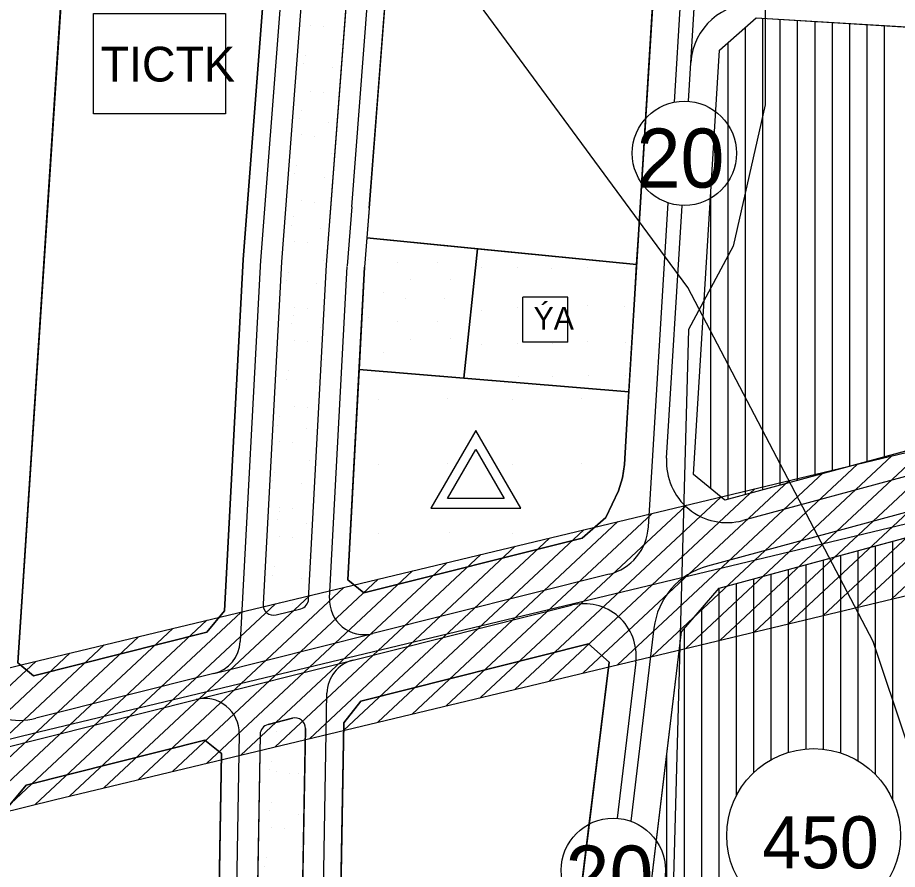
# Model space of a CAD drawing. Extents: x 419109 to 421295, y 4452223 to 4457798.
# Drawn here: x 420098 to 420351.1, y 4452707.6 to 4452952.7 of the extents above; entities that cross this region are included whole.
import ezdxf

# ---------------------------------------------------------------- set-up
doc = ezdxf.new("R2010")
doc.units = 0
for name, color, linetype in [('ADA', 7, 'Continuous'), ('ADAKENARI', 7, 'Continuous'), ('Default', 7, 'Continuous'), ('KALDIRIM', 7, 'Continuous'), ('KD_DAIRE', 7, 'Continuous'), ('KD_YGEN', 7, 'Continuous'), ('LJ_SEMBOL', 7, 'Continuous'), ('PL_AYA_PARK_DINLENME', 7, 'Continuous'), ('PL_EĞİTİM', 7, 'Continuous'), ('PL_KON_MEV_450', 7, 'Continuous'), ('PL_SAY_DINI_TESIS', 7, 'Continuous'), ('PL_TİCK', 7, 'Continuous'), ('PL_TURZM', 7, 'Continuous'), ('SM_DAIRE', 7, 'Continuous'), ('SM_SEMBOL', 7, 'Continuous'), ('SM_TAKS', 7, 'Continuous'), ('SN_3_DERECE_KAYNAK_KORUMA', 7, 'Continuous'), ('SN_KENTSEL_DONUSUM', 7, 'Continuous'), ('TA_ENH_154', 7, 'Continuous'), ('TA_ENH_KORUMA', 7, 'Continuous'), ('TA_ENH_TARAMA', 7, 'Continuous'), ('TR_DINITESIS', 7, 'Continuous'), ('TR_EĞİTİM', 7, 'Continuous'), ('TR_PARKALANI', 7, 'Continuous'), ('TR_TİC_TURIZM_K', 7, 'Continuous'), ('TR_TİCK', 7, 'Continuous'), ('TR_YUKSEKYOGUNKONUT', 7, 'Continuous')]:
    doc.layers.add(name, color=color, linetype=linetype)

# ---------------------------------------------------------------- blocks, each defined once
blk = doc.blocks.new('POINT_DISPLAY')
at = {"layer": 'Default'}
blk.add_line((0, 0), (0, 0), dxfattribs=at)

msp = doc.modelspace()

# ---------------------------------------------------------------- linework, layer by layer
at = {"layer": 'ADA'}
for p, q in [((420276.06, 4452881.68), (420198.46, 4452889.32)), ((420226.35, 4452848.98), (420230.3, 4452886.18)), ((420196.24, 4452851.48), (420273.81, 4452845.03))]:
    msp.add_line(p, q, dxfattribs=at)
at = {"layer": 'ADAKENARI'}
for p, q in [((420186.83, 4452881.59), (420205.2, 4453121.18)), ((420199.11, 4452897.8), (420215.59, 4453112.73)), ((420098.01, 4452767.09), (420110.56, 4452958.8)), ((420280.84, 4452959.33), (420276.59, 4452890.16)), ((420168.41, 4452955.24), (420162.88, 4452883.12)), ((420179.38, 4452954.4), (420173.86, 4452882.42)), ((420299.89, 4452943.25), (420310.49, 4452952.62)), ((420310.49, 4452952.62), (420548.29, 4452938.03)), ((420292.38, 4452821.22), (420299.89, 4452943.25)), ((420199.11, 4452897.8), (420197.81, 4452880.85)), ((420276.59, 4452890.16), (420275.54, 4452873.19)), ((420162.88, 4452883.12), (420157.49, 4452782.05)), ((420173.86, 4452882.39), (420168.6, 4452783.92)), ((420181.7, 4452785.39), (420186.83, 4452881.58)), ((420193.01, 4452790.98), (420197.81, 4452880.85)), ((420536.54, 4452877.47), (420301.42, 4452813.85)), ((420275.54, 4452873.19), (420273.34, 4452837.5)), ((420273.34, 4452837.5), (420272.52, 4452824.14)), ((420299.79, 4452788.55), (420467.87, 4452834.02)), ((420272.52, 4452824.14), (420271.98, 4452820.26)), ((420271.98, 4452820.26), (420270.86, 4452816.52)), ((420301.42, 4452813.85), (420292.38, 4452821.22)), ((420270.86, 4452816.52), (420267.24, 4452808.87)), ((420267.24, 4452808.87), (420260.35, 4452802.96)), ((420260.35, 4452802.96), (420197.6, 4452787.2)), ((420197.6, 4452787.2), (420193.01, 4452790.98)), ((420288.95, 4452776.01), (420299.79, 4452788.55)), ((420172.33, 4452780.85), (420179.44, 4452782.64)), ((420157.49, 4452782.05), (420152.37, 4452775.84)), ((420152.37, 4452775.84), (420102.54, 4452763.32)), ((420274.78, 4452657.74), (420288.95, 4452776.01)), ((420196.74, 4452756.05), (420262.23, 4452772.51)), ((420262.23, 4452772.51), (420268.17, 4452767.26)), ((420268.17, 4452767.26), (420253.7, 4452650.28)), ((420102.54, 4452763.32), (420098.01, 4452767.09)), ((420191.81, 4452749.84), (420196.74, 4452756.05)), ((420170.01, 4452749.34), (420177.05, 4452751.11)), ((420189.7, 4452630.41), (420191.81, 4452749.84)), ((420180.78, 4452748.14), (420178.58, 4452623.54)), ((420100.48, 4452731.87), (420151.88, 4452744.79)), ((420151.88, 4452744.79), (420156.65, 4452741.01)), ((420167.74, 4452746.48), (420165.55, 4452622.42)), ((420156.65, 4452741.01), (420154.5, 4452619.21)), ((420095.3, 4452725.67), (420100.48, 4452731.87))]:
    msp.add_line(p, q, dxfattribs=at)
for centre, start, end in [((420178.7, 4452785.55), 284.1002, 356.9459), ((420171.6, 4452783.76), 176.9459, 284.1002), ((420177.78, 4452748.2), 358.9885, 104.1002), ((420170.74, 4452746.43), 104.1002, 178.9885)]:
    msp.add_arc(centre, 3, start, end, dxfattribs=at)
at = {"layer": 'KALDIRIM'}
for p, q in [((420194.12, 4452898.18), (420210.76, 4453115.13)), ((420286.95, 4452928.36), (420293.22, 4453030.14)), ((420290.97, 4452928.59), (420294.36, 4452983.67)), ((420173.39, 4452954.86), (420167.87, 4452882.74)), ((420279.43, 4452806.17), (420285.17, 4452899.37)), ((420194.12, 4452898.18), (420192.82, 4452881.23)), ((420284.65, 4452825.91), (420289.13, 4452898.65)), ((420167.87, 4452882.85), (420162.02, 4452773.16)), ((420187.73, 4452785.7), (420192.82, 4452881.11)), ((420386.64, 4452829.66), (420306.61, 4452808.01)), ((420389.04, 4452819.95), (420296.48, 4452794.91)), ((420268.11, 4452792.54), (420200.15, 4452775.47)), ((420194.52, 4452767.87), (420257.27, 4452783.63)), ((420154.47, 4452764), (420200.15, 4452775.47)), ((420281.01, 4452777.01), (420274.36, 4452721.52)), ((420149.31, 4452756.51), (420194.52, 4452767.87)), ((420275.82, 4452767.3), (420270.43, 4452722.35)), ((420154.47, 4452764), (420103.22, 4452751.12)), ((420184.7, 4452630.5), (420186.96, 4452758.35)), ((420090.4, 4452741.72), (420149.31, 4452756.51)), ((420161.75, 4452746.64), (420159.49, 4452619.12))]:
    msp.add_line(p, q, dxfattribs=at)
for centre, radius, start, end in [((420309.63, 4452938.65), 18, 86.4895, 176.4779), ((420302.06, 4452824.84), 17.44, 176.4779, 285.1389), ((420264.46, 4452807.09), 15, 284.1002, 356.4779), ((420302.01, 4452774.49), 21.15, 105.1389, 173.1692), ((420197.71, 4452785.17), 10, 176.9459, 284.1002), ((420260.92, 4452769.08), 15, 353.1692, 104.1002), ((420152.03, 4452773.69), 10, 284.1002, 356.9459), ((420098.35, 4452770.52), 20, 176.3547, 284.1002), ((420196.96, 4452758.17), 10, 104.1002, 178.9885), ((420151.75, 4452746.81), 10, 358.9885, 104.1002)]:
    msp.add_arc(centre, radius, start, end, dxfattribs=at)
at = {"layer": 'KD_DAIRE'}
for centre in [(420289.8, 4452913.63), (420269.34, 4452707.39)]:
    msp.add_circle(centre, 15, dxfattribs=at)
at = {"layer": 'LJ_SEMBOL'}
msp.add_lwpolyline([(420119.83, 4452953.88), (420157.76, 4452953.88), (420157.76, 4452924.95), (420119.83, 4452924.95)], close=True, dxfattribs=at)
for points in [[(420242.72, 4452811.58), (420229.77, 4452833.9), (420216.83, 4452811.58), (420242.72, 4452811.58)], [(420229.77, 4452828.42), (420237.94, 4452814.33), (420221.6, 4452814.33), (420229.77, 4452828.42)]]:
    msp.add_lwpolyline(points, dxfattribs=at)
at = {"layer": 'PL_AYA_PARK_DINLENME'}
for p, q in [((420173.86, 4452882.39), (420173.86, 4452882.42)), ((420186.83, 4452881.58), (420186.83, 4452881.59)), ((420177.05, 4452751.11), (420170.01, 4452749.34))]:
    msp.add_line(p, q, dxfattribs=at)
for points in [[(420192.37, 4453123.86), (420181.82, 4452986.31), (420179.38, 4452954.4), (420173.86, 4452882.42)], [(420181.7, 4452785.39), (420186.83, 4452881.58), (420205.2, 4453121.18)], [(420198.46, 4452889.32), (420197.81, 4452880.85), (420196.24, 4452851.48), (420226.35, 4452848.98), (420230.3, 4452886.18), (420198.46, 4452889.32)], [(420173.86, 4452882.42), (420173.86, 4452882.39), (420168.6, 4452783.92)], [(420172.33, 4452780.85), (420179.44, 4452782.64)], [(420221.98, 4452467.28), (420213.84, 4452479.19), (420203.09, 4452493.61), (420194.84, 4452512.71), (420190.3, 4452526.4), (420187.84, 4452538.01), (420184.31, 4452554.71), (420180.74, 4452571.59), (420178.77, 4452588.31), (420178.65, 4452601.88), (420178.58, 4452623.54), (420180.78, 4452748.14)], [(420167.74, 4452746.48), (420165.55, 4452622.42), (420165.66, 4452600.54), (420165.78, 4452587.49), (420167.9, 4452569.48), (420177.73, 4452523), (420182.68, 4452508.07), (420190.47, 4452490.05), (420208.04, 4452455.12), (420231.59, 4452419.21), (420246, 4452397.23), (420275.85, 4452353.52), (420315.27, 4452293.39)]]:
    msp.add_lwpolyline(points, dxfattribs=at)
for centre, start, end in [((420178.7, 4452785.55), 284.1002, 356.9459), ((420171.6, 4452783.76), 176.9459, 284.1002), ((420177.78, 4452748.2), 358.9885, 104.1002), ((420170.74, 4452746.43), 104.1002, 178.9885)]:
    msp.add_arc(centre, 3, start, end, dxfattribs=at)
at = {"layer": 'PL_EĞİTİM'}
msp.add_lwpolyline([(420196.24, 4452851.48), (420193.01, 4452790.98), (420197.6, 4452787.2), (420260.35, 4452802.96), (420267.24, 4452808.87), (420270.86, 4452816.52), (420271.98, 4452820.26), (420272.52, 4452824.14), (420273.34, 4452837.5), (420273.81, 4452845.03), (420226.35, 4452848.98), (420196.24, 4452851.48)], dxfattribs=at)
at = {"layer": 'PL_KON_MEV_450'}
for points in [[(420310.49, 4452952.62), (420548.29, 4452938.03), (420556.21, 4452927.64), (420548.25, 4452889.86), (420536.54, 4452877.47), (420301.42, 4452813.85), (420292.38, 4452821.22), (420299.89, 4452943.25)], [(420299.79, 4452788.55), (420467.87, 4452834.02), (420464.63, 4452792.44), (420385.14, 4452799.11), (420376.66, 4452726.13), (420364.66, 4452632.46), (420451.75, 4452625.1), (420449.42, 4452575.56), (420449.42, 4452560.62), (420361.09, 4452604.42), (420282.55, 4452643.37), (420274.78, 4452657.74), (420288.95, 4452776.01)]]:
    msp.add_lwpolyline(points, close=True, dxfattribs=at)
at = {"layer": 'PL_SAY_DINI_TESIS'}
msp.add_lwpolyline([(420273.81, 4452845.03), (420275.54, 4452873.19), (420276.06, 4452881.68), (420230.3, 4452886.18), (420226.35, 4452848.98), (420273.81, 4452845.03)], dxfattribs=at)
at = {"layer": 'PL_TİCK'}
for points in [[(420276.06, 4452881.68), (420276.59, 4452890.16), (420280.84, 4452959.33), (420282.07, 4452979.3), (420284.65, 4453021.25), (420285.88, 4453041.22), (420287.88, 4453073.74), (420279.7, 4453088.47), (420225.15, 4453117.94), (420215.59, 4453112.73), (420199.11, 4452897.8), (420198.46, 4452889.32), (420230.3, 4452886.18), (420276.06, 4452881.68)], [(420253.7, 4452650.28), (420268.17, 4452767.26), (420262.23, 4452772.51), (420196.74, 4452756.05), (420191.81, 4452749.84), (420189.7, 4452630.41), (420189.6, 4452607.8), (420189.77, 4452589), (420190.03, 4452586.79), (420276.74, 4452528.45)]]:
    msp.add_lwpolyline(points, dxfattribs=at)
at = {"layer": 'PL_TURZM'}
for points in [[(420122.39, 4453139.62), (420122.16, 4453136.1), (420112.64, 4452990.73), (420110.56, 4452958.8), (420098.01, 4452767.09), (420102.54, 4452763.32), (420152.37, 4452775.84), (420157.49, 4452782.05), (420162.88, 4452883.12), (420168.41, 4452955.24), (420170.86, 4452987.15), (420181.47, 4453125.59), (420181.74, 4453129.1), (420177.2, 4453134.96), (420127.64, 4453143.73), (420122.39, 4453139.62)], [(420225.97, 4452407.72), (420222.39, 4452413.18), (420198.5, 4452449.62), (420180.5, 4452485.39), (420172.39, 4452504.15), (420167.1, 4452520.12), (420157.04, 4452567.7), (420154.79, 4452586.79), (420154.7, 4452596.71), (420154.5, 4452619.21), (420156.65, 4452741.01), (420151.88, 4452744.79), (420100.48, 4452731.87), (420095.3, 4452725.67)]]:
    msp.add_lwpolyline(points, dxfattribs=at)
at = {"layer": 'SM_DAIRE'}
msp.add_circle((420326.96, 4452717.38), 25, dxfattribs=at)
at = {"layer": 'SM_SEMBOL'}
for points in [[(420256.29, 4452872.28), (420243.29, 4452872.28)], [(420243.29, 4452859.28), (420243.29, 4452872.28)], [(420256.29, 4452859.28), (420256.29, 4452872.28)], [(420256.29, 4452859.28), (420243.29, 4452859.28)]]:
    msp.add_lwpolyline(points, dxfattribs=at)
at = {"layer": 'SN_3_DERECE_KAYNAK_KORUMA'}
msp.add_lwpolyline([(420357.81, 4452232.59), (420364.57, 4452258.77), (420388.14, 4452395.87), (420395.04, 4452520.02), (420383.4, 4452655.62), (420344.11, 4452773.22), (420290.77, 4452875.07), (420213.22, 4452980.45), (420010.57, 4453225.26), (419772.92, 4453473.96), (419554.68, 4453657.1), (419332.55, 4453805.23), (419159.82, 4453894.89), (419126.5, 4453906.07)], dxfattribs=at)
at = {"layer": 'SN_KENTSEL_DONUSUM'}
for p, q in [((420313.06, 4453004.98), (420313.06, 4452927.53)), ((420313.06, 4452927.53), (420303.84, 4452886.96)), ((420303.84, 4452886.96), (420290.93, 4452862.98)), ((420290.93, 4452862.98), (420285.4, 4452658.29))]:
    msp.add_line(p, q, dxfattribs=at)
at = {"layer": 'TA_ENH_154'}
msp.add_lwpolyline([(421244.23, 4452871.73), (420603.45, 4452866.93), (420104.11, 4452747.15), (419709.07, 4452649.72), (419353.3, 4452559.56), (419284.53, 4452601.29), (419287.68, 4452599.87), (419484.08, 4452691.72), (419833.95, 4454863.94), (419862.83, 4455014.24)], dxfattribs=at)
at = {"layer": 'TA_ENH_KORUMA'}
msp.add_lwpolyline([(419883.15, 4455014.02), (419853.65, 4454860.46), (419502.14, 4452678.09), (419329.55, 4452597.37), (419356.51, 4452581.01), (419704.22, 4452669.12), (420099.38, 4452766.58), (420601.01, 4452886.92), (421244.44, 4452891.74)], dxfattribs=at)
at = {"layer": 'TA_ENH_TARAMA'}
for p, q in [((420108.84, 4452727.71), (420605.89, 4452846.95)), ((420349.39, 4452785.42), (420408.61, 4452840.76)), ((420339.54, 4452783.05), (420398.76, 4452838.4)), ((420329.69, 4452780.69), (420388.91, 4452836.03)), ((420319.83, 4452778.33), (420379.05, 4452833.67)), ((420309.98, 4452775.96), (420369.2, 4452831.31)), ((420300.13, 4452773.6), (420359.35, 4452828.94)), ((420290.28, 4452771.24), (420349.5, 4452826.58)), ((420280.42, 4452768.87), (420339.64, 4452824.22)), ((420270.57, 4452766.51), (420329.79, 4452821.85)), ((420260.72, 4452764.15), (420319.94, 4452819.49)), ((420250.87, 4452761.78), (420310.09, 4452817.13)), ((420241.02, 4452759.42), (420300.23, 4452814.76)), ((420231.16, 4452757.06), (420290.38, 4452812.4)), ((420211.46, 4452752.33), (420270.68, 4452807.67)), ((420221.31, 4452754.69), (420280.53, 4452810.04)), ((420201.61, 4452749.96), (420260.82, 4452805.31)), ((420191.75, 4452747.6), (420250.97, 4452802.95)), ((420181.9, 4452745.24), (420241.12, 4452800.58)), ((420172.05, 4452742.87), (420231.27, 4452798.22)), ((420162.2, 4452740.51), (420221.42, 4452795.86)), ((420152.34, 4452738.15), (420211.56, 4452793.49)), ((420142.49, 4452735.78), (420201.71, 4452791.13)), ((420132.64, 4452733.42), (420191.86, 4452788.77)), ((420122.79, 4452731.06), (420182.01, 4452786.4)), ((420112.93, 4452728.69), (420172.15, 4452784.04)), ((420103.03, 4452726.28), (420162.3, 4452781.68)), ((420093.08, 4452723.82), (420152.45, 4452779.31)), ((420083.13, 4452721.37), (420142.6, 4452776.95)), ((420063.23, 4452716.46), (420122.89, 4452772.22)), ((420073.18, 4452718.92), (420132.74, 4452774.58)), ((420053.28, 4452714.01), (420113.04, 4452769.86)), ((420043.33, 4452711.56), (420103.19, 4452767.49)), ((419713.92, 4452630.31), (420108.84, 4452727.71))]:
    msp.add_line(p, q, dxfattribs=at)
at = {"layer": 'TR_TİC_TURIZM_K'}
for points in [[(420127.64, 4453143.73), (420122.39, 4453139.62), (420122.16, 4453136.1), (420112.64, 4452990.73), (420110.56, 4452958.8), (420098.01, 4452767.09), (420102.54, 4452763.32), (420152.37, 4452775.84), (420157.49, 4452782.05), (420162.88, 4452883.12), (420168.41, 4452955.24), (420170.86, 4452987.15), (420181.47, 4453125.59), (420181.74, 4453129.1), (420177.2, 4453134.96), (420127.64, 4453143.73)], [(420119.83, 4452924.95), (420119.83, 4452953.88), (420157.76, 4452953.88), (420157.76, 4452924.95), (420119.83, 4452924.95)], [(420093.03, 4452576.93), (420100.03, 4452536.75), (420107.76, 4452506.59), (420114.48, 4452486.76), (420120.64, 4452471), (420129.77, 4452449.56), (420138.18, 4452433.13), (420173.92, 4452366.16), (420177.01, 4452360.38), (420225.97, 4452407.72), (420222.39, 4452413.18), (420198.5, 4452449.62), (420180.5, 4452485.39), (420172.39, 4452504.15), (420167.1, 4452520.12), (420157.04, 4452567.7), (420154.79, 4452586.79), (420154.7, 4452596.71), (420154.5, 4452619.21), (420156.65, 4452741.01), (420151.88, 4452744.79), (420100.48, 4452731.87), (420095.3, 4452725.67)]]:
    msp.add_lwpolyline(points, dxfattribs=at)
at = {"layer": 'TR_TİCK'}
for points in [[(420276.06, 4452881.68), (420276.59, 4452890.16), (420280.84, 4452959.33), (420282.07, 4452979.3), (420284.65, 4453021.25), (420285.88, 4453041.22), (420287.88, 4453073.74), (420279.7, 4453088.47), (420225.15, 4453117.94), (420215.59, 4453112.73), (420199.11, 4452897.8), (420198.46, 4452889.32), (420230.3, 4452886.18), (420276.06, 4452881.68)], [(420253.7, 4452650.28), (420268.17, 4452767.26), (420262.23, 4452772.51), (420196.74, 4452756.05), (420191.81, 4452749.84), (420189.7, 4452630.41), (420189.6, 4452607.8), (420189.77, 4452589), (420190.03, 4452586.79), (420276.74, 4452528.45)]]:
    msp.add_lwpolyline(points, dxfattribs=at)
at = {"layer": 'TR_YUKSEKYOGUNKONUT'}
for p, q in [((420312.38, 4452816.82), (420312.38, 4452952.51)), ((420317.38, 4452818.17), (420317.38, 4452952.2)), ((420322.38, 4452819.53), (420322.38, 4452951.89)), ((420307.38, 4452815.47), (420307.38, 4452949.88)), ((420327.38, 4452820.88), (420327.38, 4452951.59)), ((420332.38, 4452822.23), (420332.38, 4452951.28)), ((420337.38, 4452823.58), (420337.38, 4452950.97)), ((420342.38, 4452824.94), (420342.38, 4452950.67)), ((420347.38, 4452826.29), (420347.38, 4452950.36)), ((420302.38, 4452814.11), (420302.38, 4452945.45)), ((420297.38, 4452817.15), (420297.38, 4452902.46)), ((420344.78, 4452734.92), (420344.78, 4452800.72)), ((420349.78, 4452727.59), (420349.78, 4452802.08)), ((420334.78, 4452741.13), (420334.78, 4452798.02)), ((420339.78, 4452738.84), (420339.78, 4452799.37)), ((420324.78, 4452742.29), (420324.78, 4452795.31)), ((420329.78, 4452742.22), (420329.78, 4452796.66)), ((420314.78, 4452739.21), (420314.78, 4452792.61)), ((420319.78, 4452741.33), (420319.78, 4452793.96)), ((420304.78, 4452728.91), (420304.78, 4452789.9)), ((420309.78, 4452735.54), (420309.78, 4452791.25)), ((420299.78, 4452634.82), (420299.78, 4452788.54)), ((420294.78, 4452637.3), (420294.78, 4452782.76)), ((420289.78, 4452639.78), (420289.78, 4452776.97)), ((420284.78, 4452642.26), (420284.78, 4452741.22))]:
    msp.add_line(p, q, dxfattribs=at)

# ---------------------------------------------------------------- block references
at = {"layer": 'TR_DINITESIS', "xscale": 0.1, "yscale": 0.10000000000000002}
for p in [(420231.5, 4452880.81), (420241.75, 4452880.81), (420251.51, 4452880.62), (420261.85, 4452880.81), (420272.49, 4452880.78), (420231.5, 4452868.52), (420241.75, 4452869.34), (420251.51, 4452869.43), (420261.85, 4452869.72), (420272.49, 4452869.59), (420231.5, 4452858.52), (420241.75, 4452859.01), (420251.89, 4452859.01), (420261.85, 4452859.48), (420272.87, 4452859.17), (420231.82, 4452848.51), (420242.07, 4452849.33), (420251.84, 4452849.43), (420262.17, 4452849.71), (420272.81, 4452849.59)]:
    msp.add_blockref('POINT_DISPLAY', p, dxfattribs=at)
at = {"layer": 'TR_EĞİTİM', "xscale": 0.1, "yscale": 0.10000000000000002}
for p in [(420201.92, 4452842.77), (420221.67, 4452843), (420240.48, 4452842.77), (420260.23, 4452843), (420201.92, 4452824.19), (420221.67, 4452824.41), (420240.48, 4452824.19), (420260.23, 4452824.41), (420201.92, 4452804.19), (420222.12, 4452804.5), (420240.48, 4452804.19), (420260.68, 4452804.5)]:
    msp.add_blockref('POINT_DISPLAY', p, dxfattribs=at)
at = {"layer": 'TR_PARKALANI', "xscale": 0.1, "yscale": 0.10000000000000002}
for p in [(420182.2, 4452950.51), (420185.96, 4452950.17), (420190.8, 4452945.04), (420180.17, 4452939.33), (420180.7, 4452941.67), (420188.6, 4452938.28), (420182.2, 4452931.51), (420185.96, 4452931.18), (420179.57, 4452925.97), (420179.04, 4452923.63), (420187.47, 4452922.58), (420179.76, 4452918.92), (420183.51, 4452918.58), (420188.35, 4452913.45), (420178.25, 4452910.08), (420177.73, 4452907.74), (420186.15, 4452906.69), (420179.76, 4452899.92), (420183.51, 4452899.59), (420177.31, 4452895.32), (420176.79, 4452892.98), (420185.21, 4452891.93), (420177.5, 4452888.27), (420181.26, 4452887.93), (420186.1, 4452882.8), (420198.98, 4452883.2), (420207.4, 4452882.16), (420218.68, 4452882.16), (420176, 4452879.43), (420175.47, 4452877.09), (420183.9, 4452876.04), (420211.12, 4452877.27), (420222.4, 4452877.27), (420203.26, 4452873.54), (420209.6, 4452871.99), (420220.88, 4452871.99), (420177.5, 4452869.28), (420181.26, 4452868.94), (420177.31, 4452866.92), (420198.98, 4452866.28), (420176.79, 4452864.59), (420185.21, 4452863.54), (420207.4, 4452865.23), (420218.68, 4452865.23), (420177.5, 4452859.87), (420181.26, 4452859.54), (420211.12, 4452859.97), (420222.4, 4452860.35), (420196.35, 4452857.37), (420203.26, 4452856.25), (420186.1, 4452854.41), (420176, 4452851.04), (420175.47, 4452848.7), (420183.9, 4452847.65), (420177.5, 4452840.88), (420181.26, 4452840.54), (420172.65, 4452835.44), (420173.18, 4452837.78), (420181.08, 4452834.4), (420173.37, 4452830.73), (420177.12, 4452830.39), (420181.96, 4452825.26), (420171.86, 4452821.89), (420171.33, 4452819.55), (420179.76, 4452818.51), (420173.18, 4452810.51), (420173.37, 4452811.74), (420177.12, 4452811.4), (420172.65, 4452808.18), (420181.08, 4452807.13), (420173.37, 4452803.46), (420177.12, 4452803.13), (420181.96, 4452798), (420171.86, 4452794.63), (420171.33, 4452792.29), (420179.76, 4452791.24), (420173.37, 4452784.47), (420177.12, 4452784.13), (420172.43, 4452747.43), (420176.18, 4452747.09), (420170.92, 4452738.59), (420170.39, 4452736.25), (420172.43, 4452735.68), (420176.18, 4452735.34), (420178.82, 4452735.21), (420170.92, 4452726.84), (420170.39, 4452724.5), (420178.82, 4452723.46), (420171.11, 4452719.79), (420174.86, 4452719.45), (420179.71, 4452714.32), (420169.61, 4452710.95), (420169.08, 4452708.61)]:
    msp.add_blockref('POINT_DISPLAY', p, dxfattribs=at)

# ---------------------------------------------------------------- texts
at = {"layer": 'KD_YGEN'}
for p in [(420276.03, 4452903.74), (420255.58, 4452697.49)]:
    msp.add_text('20', height=17, dxfattribs=at).set_placement(p)
at = {"layer": 'LJ_SEMBOL'}
msp.add_text('TICTK', height=10, dxfattribs=at).set_placement((420121.86, 4452934.27))
at = {"layer": 'SM_SEMBOL'}
msp.add_text('ÝA', height=6.5, dxfattribs=at).set_placement((420246.41, 4452862.91))
at = {"layer": 'SM_TAKS'}
msp.add_text('450', height=15, dxfattribs=at).set_placement((420312.22, 4452707.94))

doc.saveas('drawing.dxf')
